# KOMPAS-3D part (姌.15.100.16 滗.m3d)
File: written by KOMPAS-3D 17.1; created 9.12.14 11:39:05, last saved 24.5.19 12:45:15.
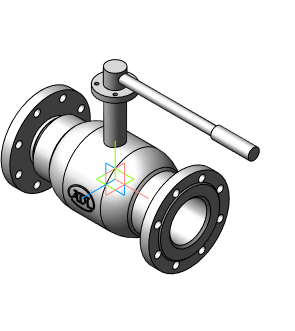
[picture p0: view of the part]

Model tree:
1. Операция без истории:3  (labels: Сталь 20  ГОСТ 1050-88)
